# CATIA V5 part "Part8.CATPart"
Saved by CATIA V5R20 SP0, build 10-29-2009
Part number: 1DIN7984516_DIN 7984 - M5 x 16 --- 16C
Revision: ANY
Definition: UNKNOWN
Nomenclature: 1DIN7984516_DIN 7984 - M5 x 16 --- 16C
Source: Unknown
Bounding box of the stored display mesh (mm): x 0 to 19.5, y -4.25 to 4.25, z -4.25 to 4.25
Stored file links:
  C:\Users\Utente\Desktop\IO LAVORO\3D X SITO CF\CUMSA\3D files PW\pw080825\pw080825_injection\Part8.CATPart
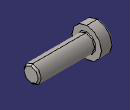
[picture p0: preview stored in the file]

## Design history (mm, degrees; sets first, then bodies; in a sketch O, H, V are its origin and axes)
Body1 "Hex" (main body)
  Solid1: solid without history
